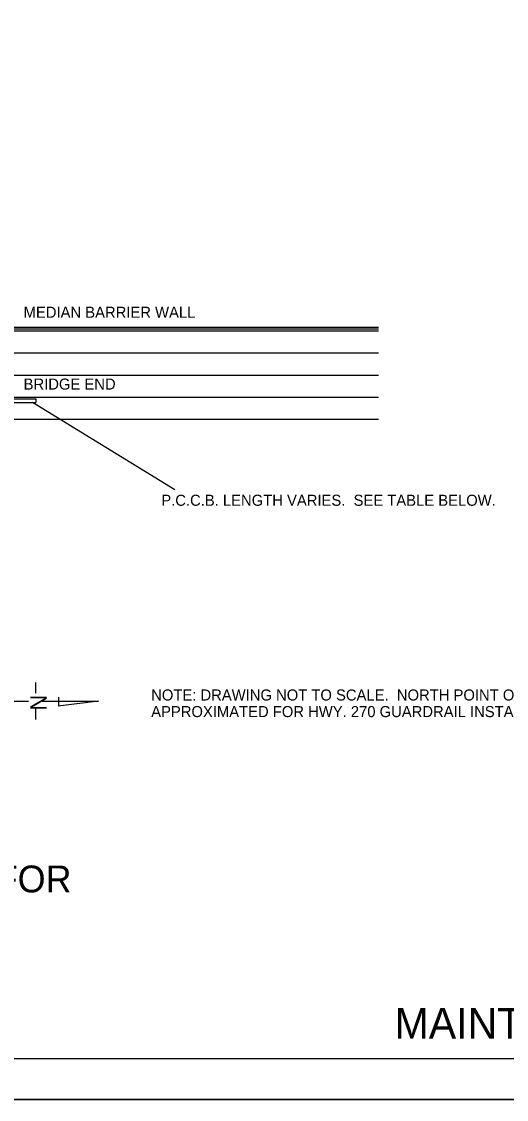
# Model space of a CAD drawing. Extents: x 1397271 to 1411271, y 376395 to 377888.
# Drawn here: x 1410415 to 1410746, y 376395 to 377132 of the extents above; entities that cross this region are included whole.
import ezdxf

# ---------------------------------------------------------------- set-up
doc = ezdxf.new("R2010")
doc.units = 0
for name, color, linetype in [('Default', 7, 'Continuous'), ('R_Border', 7, 'Continuous'), ('R_Dimension', 7, 'Continuous'), ('R_Draft', 7, 'Continuous'), ('R_Horz Alg', 7, 'Continuous'), ('R_MOT', 7, 'Continuous'), ('R_No Plot', 7, 'Continuous')]:
    doc.layers.add(name, color=color, linetype=linetype)

msp = doc.modelspace()

# ---------------------------------------------------------------- linework, layer by layer
at = {"layer": 'R_Border'}
msp.add_line((1411238.15, 376422.47), (1409024.85, 376422.47), dxfattribs=at)
at = {"layer": 'R_Dimension'}
msp.add_line((1410519.4, 376811.71), (1410422.13, 376871.35), dxfattribs=at)
at = {"layer": 'R_Draft'}
for p, q in [((1410424.06, 376679.87), (1410424.06, 376672.54)), ((1410439.82, 376669.84), (1410439.82, 376663.7)), ((1410407.88, 376667.16), (1410419.25, 376667.16)), ((1410424.06, 376662.28), (1410424.06, 376654.45)), ((1410428.61, 376667.16), (1410467.26, 376667.16)), ((1410467.26, 376667.16), (1410439.62, 376663.7))]:
    msp.add_line(p, q, dxfattribs=at)
at = {"layer": 'R_Horz Alg'}
for p, q in [((1410658.78, 376921.48), (1409636.72, 376921.48)), ((1410658.78, 376922.74), (1410245.24, 376922.74)), ((1410658.78, 376920.22), (1410245.24, 376920.22)), ((1410658.78, 376905.09), (1409636.72, 376905.09)), ((1410658.78, 376889.96), (1409636.72, 376889.96)), ((1410658.78, 376874.83), (1409636.72, 376874.83)), ((1410658.78, 376859.7), (1410373.56, 376859.7))]:
    msp.add_line(p, q, dxfattribs=at)
at = {"layer": 'R_MOT'}
for p, q in [((1410399.06, 376873.87), (1410424.28, 376873.87)), ((1410399.06, 376871.35), (1410424.28, 376871.35)), ((1410424.28, 376873.87), (1410424.28, 376871.35))]:
    msp.add_line(p, q, dxfattribs=at)
at = {"layer": 'R_No Plot'}
msp.add_line((1408938.04, 376394.62), (1411271.41, 376394.62), dxfattribs=at)
for points in [[(1408937.99, 377887.98), (1411271.41, 377887.98), (1411271.41, 376394.59), (1408937.99, 376394.59)], [(1410662.32, 377860.72), (1410662.32, 377791.56), (1410912.44, 377791.56), (1410912.44, 377771.12), (1411074.84, 377771.12), (1411074.84, 377600.79), (1411238.15, 377600.79), (1411238.15, 376422.47), (1409024.85, 376422.47), (1409024.85, 377860.72)]]:
    msp.add_lwpolyline(points, close=True, dxfattribs=at)

# ---------------------------------------------------------------- texts
at = {"layer": 'Default'}
msp.add_text('PRECAST CONCRETE BARRIER WALL PLACEMENT FOR', height=18.3753, dxfattribs=at).set_placement((1409782.46, 376536.23))
at = {"layer": 'R_Border'}
for s, height, p in [('MEDIAN BARRIER WALL', 7.5652, (1410415.97, 376929.37)), ('BRIDGE END', 7.565, (1410415.97, 376880.21)), ('P.C.C.B. LENGTH VARIES.  SEE TABLE BELOW.', 7.5652, (1410510.16, 376800.73)), ('NOTE: DRAWING NOT TO SCALE.  NORTH POINT ORIENTATION ', 7.5652, (1410503.23, 376667.51)), ('APPROXIMATED FOR HWY. 270 GUARDRAIL INSTALLATION OPERATIONS.  ', 7.5652, (1410503.23, 376656.16)), ('MAINTENANCE OF TRAFFIC DETAILS', 21.0004, (1410669.75, 376436.19))]:
    msp.add_text(s, height=height, dxfattribs=at).set_placement(p)
at = {"layer": 'R_Draft'}
msp.add_text('N', height=11.05, rotation=270, dxfattribs=at).set_placement((1410420.65, 376671.35))

doc.saveas('drawing.dxf')
